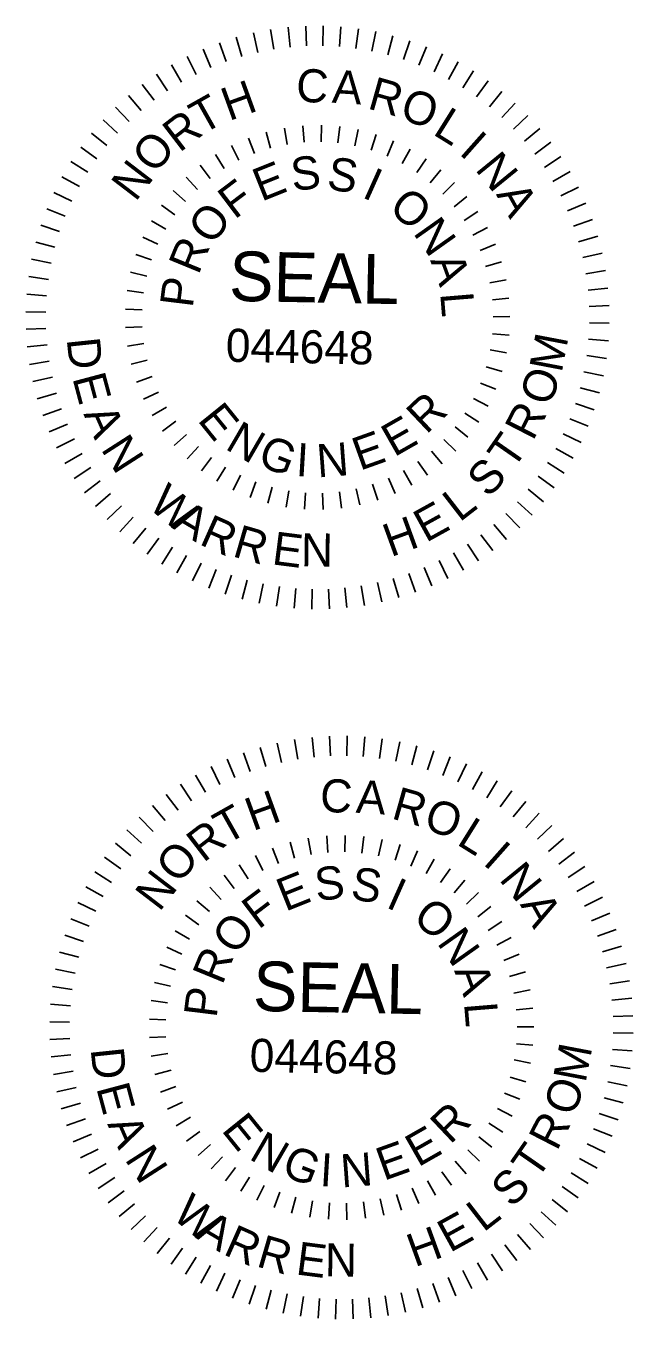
# Model space of a CAD drawing. Extents: x 0 to 7954, y -383 to 1504.
# Drawn here: x 3.6853 to 3.812, y 1.3954 to 1.6653 of the extents above; entities that cross this region are included whole.
import ezdxf

# ---------------------------------------------------------------- set-up
doc = ezdxf.new("R2010")
doc.units = 0
doc.layers.add('UBO Plan Sheet 34 CELL', color=7, linetype='Continuous')

msp = doc.modelspace()

# ---------------------------------------------------------------- linework, layer by layer
at = {"layer": 'UBO Plan Sheet 34 CELL'}
for p, q in [((3.74738, 1.66527), (3.7473, 1.66112)), ((3.72922, 1.66288), (3.73037, 1.65888)), ((3.73279, 1.66379), (3.73369, 1.65974)), ((3.73639, 1.66449), (3.73706, 1.6604)), ((3.74004, 1.66497), (3.74045, 1.66085)), ((3.7437, 1.66523), (3.74387, 1.66109)), ((3.75106, 1.66508), (3.75073, 1.66095)), ((3.75471, 1.66468), (3.75413, 1.66057)), ((3.75833, 1.66406), (3.7575, 1.65999)), ((3.76191, 1.66322), (3.76084, 1.65921)), ((3.7223, 1.6604), (3.72392, 1.65659)), ((3.72572, 1.66175), (3.72712, 1.65783)), ((3.76544, 1.66216), (3.76412, 1.65822)), ((3.76888, 1.66089), (3.76733, 1.65704)), ((3.71896, 1.65886), (3.72082, 1.65515)), ((3.77225, 1.65941), (3.77048, 1.65566)), ((3.77552, 1.65774), (3.77352, 1.6541)), ((3.7126, 1.65518), (3.71489, 1.65172)), ((3.71572, 1.65712), (3.7178, 1.65353)), ((3.77869, 1.65587), (3.77647, 1.65236)), ((3.7096, 1.65306), (3.71209, 1.64975)), ((3.78174, 1.65381), (3.77931, 1.65045)), ((3.70672, 1.65076), (3.70941, 1.64761)), ((3.78465, 1.65158), (3.78203, 1.64836)), ((3.78743, 1.64916), (3.78462, 1.64612)), ((3.704, 1.6483), (3.70687, 1.64531)), ((3.79006, 1.64659), (3.78707, 1.64372)), ((3.70143, 1.64567), (3.70447, 1.64286)), ((3.73925, 1.64393), (3.73984, 1.64052)), ((3.74309, 1.64441), (3.74336, 1.64097)), ((3.74697, 1.64452), (3.7469, 1.64107)), ((3.7469, 1.64107), (3.74697, 1.64452)), ((3.75084, 1.64426), (3.75044, 1.64083)), ((3.79252, 1.64387), (3.78937, 1.64118)), ((3.69901, 1.64289), (3.70223, 1.64027)), ((3.73179, 1.64186), (3.73303, 1.63863)), ((3.73547, 1.64308), (3.73639, 1.63974)), ((3.75466, 1.64362), (3.75393, 1.64024)), ((3.7584, 1.64262), (3.75735, 1.63933)), ((3.76204, 1.64127), (3.76067, 1.63809)), ((3.79483, 1.64099), (3.79151, 1.6385)), ((3.69678, 1.63998), (3.70014, 1.63755)), ((3.72486, 1.6384), (3.7267, 1.63547)), ((3.72824, 1.6403), (3.72978, 1.63721)), ((3.76552, 1.63956), (3.76386, 1.63653)), ((3.69472, 1.63693), (3.69823, 1.63471)), ((3.72168, 1.63618), (3.72379, 1.63344)), ((3.76882, 1.63753), (3.76687, 1.63467)), ((3.79694, 1.63799), (3.79349, 1.6357)), ((3.69285, 1.63376), (3.69649, 1.63176)), ((3.71873, 1.63367), (3.7211, 1.63115)), ((3.77191, 1.63519), (3.76969, 1.63253)), ((3.79888, 1.63487), (3.79529, 1.63279)), ((3.69118, 1.63049), (3.69493, 1.62871)), ((3.71603, 1.63089), (3.71863, 1.62861)), ((3.77476, 1.63256), (3.77229, 1.63013)), ((3.80062, 1.63163), (3.79691, 1.62977)), ((3.71362, 1.62786), (3.71642, 1.62583)), ((3.77734, 1.62967), (3.77466, 1.6275)), ((3.80216, 1.62829), (3.79835, 1.62667)), ((3.6897, 1.62712), (3.69355, 1.62557)), ((3.77964, 1.62655), (3.77675, 1.62463)), ((3.80351, 1.62487), (3.7996, 1.62347)), ((3.68843, 1.62367), (3.69237, 1.62236)), ((3.71151, 1.62461), (3.71449, 1.62286)), ((3.78161, 1.62322), (3.77856, 1.62159)), ((3.68737, 1.62015), (3.69138, 1.61908)), ((3.70972, 1.62116), (3.71286, 1.61972)), ((3.78327, 1.6197), (3.78007, 1.61839)), ((3.80464, 1.62137), (3.80065, 1.62022)), ((3.70828, 1.61756), (3.71155, 1.61643)), ((3.80555, 1.6178), (3.80151, 1.6169)), ((3.68653, 1.61657), (3.6906, 1.61574)), ((3.78457, 1.61605), (3.78125, 1.61505)), ((3.80625, 1.6142), (3.80216, 1.61353)), ((3.68591, 1.61295), (3.69002, 1.61237)), ((3.70718, 1.61385), (3.71054, 1.61303)), ((3.78551, 1.61229), (3.78212, 1.61162)), ((3.68551, 1.60929), (3.68964, 1.60896)), ((3.70646, 1.61004), (3.70988, 1.60956)), ((3.80673, 1.61055), (3.80261, 1.61014)), ((3.7061, 1.60618), (3.70955, 1.60602)), ((3.74334, 1.60681), (3.74334, 1.60681)), ((3.78609, 1.60846), (3.78265, 1.60812)), ((3.80699, 1.60689), (3.80285, 1.60672)), ((3.68532, 1.60562), (3.68947, 1.60554)), ((3.78629, 1.60459), (3.78284, 1.60457)), ((3.80703, 1.60321), (3.80288, 1.60329)), ((3.68536, 1.60194), (3.6895, 1.60211)), ((3.70611, 1.6023), (3.70956, 1.60248)), ((3.78612, 1.60072), (3.78268, 1.60103)), ((3.68562, 1.59828), (3.68974, 1.59869)), ((3.70651, 1.59845), (3.70992, 1.59896)), ((3.80685, 1.59953), (3.80271, 1.59986)), ((3.6861, 1.59463), (3.69019, 1.5953)), ((3.70727, 1.59464), (3.71062, 1.59548)), ((3.7822, 1.59765), (3.7856, 1.59701)), ((3.80644, 1.59588), (3.80234, 1.59646)), ((3.78467, 1.59311), (3.78135, 1.59408)), ((3.80582, 1.59226), (3.80175, 1.59309)), ((3.6868, 1.59103), (3.69085, 1.59193)), ((3.70839, 1.59093), (3.71165, 1.59209)), ((3.7834, 1.58945), (3.78019, 1.59073)), ((3.80498, 1.58868), (3.80097, 1.58975)), ((3.68771, 1.58746), (3.69171, 1.58861)), ((3.70987, 1.58735), (3.713, 1.58883)), ((3.78177, 1.58593), (3.77871, 1.58752)), ((3.68884, 1.58396), (3.69276, 1.58536)), ((3.71168, 1.58393), (3.71466, 1.58569)), ((3.77983, 1.58258), (3.77693, 1.58446)), ((3.80392, 1.58515), (3.79998, 1.58647)), ((3.69019, 1.58054), (3.694, 1.58216)), ((3.71382, 1.58069), (3.71661, 1.58274)), ((3.77756, 1.57943), (3.77486, 1.58158)), ((3.80265, 1.58171), (3.7988, 1.58326)), ((3.69173, 1.5772), (3.69544, 1.57906)), ((3.71627, 1.57768), (3.71884, 1.57998)), ((3.775, 1.57652), (3.77252, 1.57892)), ((3.80117, 1.57834), (3.79742, 1.58011)), ((3.71898, 1.57492), (3.72133, 1.57746)), ((3.77218, 1.57387), (3.76994, 1.5765)), ((3.7995, 1.57507), (3.79586, 1.57707)), ((3.69347, 1.57396), (3.69706, 1.57604)), ((3.72196, 1.57244), (3.72404, 1.57519)), ((3.76911, 1.5715), (3.76713, 1.57434)), ((3.79763, 1.5719), (3.79413, 1.57412)), ((3.69541, 1.57084), (3.69887, 1.57312)), ((3.72515, 1.57025), (3.72697, 1.57319)), ((3.72856, 1.56838), (3.73007, 1.57149)), ((3.76235, 1.56771), (3.76096, 1.57087)), ((3.76583, 1.56944), (3.76413, 1.57246)), ((3.79557, 1.56885), (3.79221, 1.57128)), ((3.69753, 1.56784), (3.70084, 1.57033)), ((3.73212, 1.56684), (3.73333, 1.57008)), ((3.73668, 1.56901), (3.73578, 1.56566)), ((3.7396, 1.56484), (3.74016, 1.56825)), ((3.755, 1.56528), (3.75424, 1.56866)), ((3.75873, 1.56631), (3.75765, 1.5696)), ((3.79334, 1.56594), (3.79012, 1.56856)), ((3.69983, 1.56496), (3.70298, 1.56765)), ((3.74344, 1.56439), (3.74368, 1.56784)), ((3.74732, 1.56431), (3.74722, 1.56777)), ((3.75118, 1.56461), (3.75075, 1.56804)), ((3.79092, 1.56316), (3.78788, 1.56597)), ((3.70229, 1.56224), (3.70528, 1.56511)), ((3.70492, 1.55966), (3.70773, 1.56271)), ((3.78835, 1.56053), (3.78548, 1.56352)), ((3.7077, 1.55725), (3.71032, 1.56047)), ((3.78563, 1.55807), (3.78294, 1.56122)), ((3.71061, 1.55502), (3.71304, 1.55838)), ((3.78275, 1.55577), (3.78026, 1.55908)), ((3.71366, 1.55296), (3.71588, 1.55646)), ((3.71683, 1.55109), (3.71883, 1.55473)), ((3.77663, 1.55171), (3.77455, 1.5553)), ((3.77975, 1.55365), (3.77747, 1.5571)), ((3.7201, 1.54942), (3.72188, 1.55317)), ((3.77005, 1.54843), (3.76843, 1.55224)), ((3.77339, 1.54997), (3.77153, 1.55368)), ((3.72347, 1.54794), (3.72502, 1.55179)), ((3.72692, 1.54667), (3.72823, 1.55061)), ((3.73044, 1.54561), (3.73151, 1.54962)), ((3.76313, 1.54595), (3.76198, 1.54994)), ((3.76663, 1.54708), (3.76523, 1.55099)), ((3.73402, 1.54477), (3.73485, 1.54884)), ((3.73764, 1.54415), (3.73822, 1.54825)), ((3.7413, 1.54374), (3.74163, 1.54788)), ((3.74497, 1.54356), (3.74505, 1.54771)), ((3.74865, 1.5436), (3.74848, 1.54774)), ((3.75231, 1.54386), (3.7519, 1.54798)), ((3.75596, 1.54434), (3.75529, 1.54843)), ((3.75957, 1.54504), (3.75866, 1.54908)), ((3.74869, 1.51705), (3.74885, 1.5129)), ((3.75237, 1.51709), (3.75228, 1.51294)), ((3.75604, 1.5169), (3.75571, 1.51277)), ((3.7342, 1.51469), (3.73536, 1.5107)), ((3.73777, 1.51561), (3.73868, 1.51156)), ((3.74138, 1.51631), (3.74204, 1.51222)), ((3.74502, 1.51679), (3.74544, 1.51266)), ((3.75969, 1.5165), (3.75912, 1.51239)), ((3.76332, 1.51588), (3.76249, 1.51181)), ((3.76689, 1.51503), (3.76583, 1.51102)), ((3.72729, 1.51222), (3.72891, 1.5084)), ((3.73071, 1.51356), (3.73211, 1.50965)), ((3.77042, 1.51398), (3.76911, 1.51003)), ((3.77387, 1.51271), (3.77232, 1.50886)), ((3.72071, 1.50893), (3.72279, 1.50534)), ((3.72395, 1.51068), (3.7258, 1.50696)), ((3.77723, 1.51123), (3.77546, 1.50748)), ((3.78051, 1.50956), (3.77851, 1.50592)), ((3.71758, 1.507), (3.71987, 1.50354)), ((3.78368, 1.50769), (3.78146, 1.50418)), ((3.71458, 1.50488), (3.71707, 1.50157)), ((3.78672, 1.50563), (3.7843, 1.50226)), ((3.78964, 1.50339), (3.78702, 1.50018)), ((3.71171, 1.50258), (3.7144, 1.49942)), ((3.79242, 1.50098), (3.78961, 1.49793)), ((3.70898, 1.50011), (3.71186, 1.49712)), ((3.79504, 1.49841), (3.79205, 1.49554)), ((3.70641, 1.49749), (3.70946, 1.49468)), ((3.74424, 1.49575), (3.74483, 1.49234)), ((3.74808, 1.49623), (3.74834, 1.49278)), ((3.75196, 1.49634), (3.75189, 1.49289)), ((3.75189, 1.49289), (3.75196, 1.49634)), ((3.75583, 1.49607), (3.75542, 1.49264)), ((3.75965, 1.49544), (3.75892, 1.49206)), ((3.79751, 1.49568), (3.79435, 1.493)), ((3.704, 1.49471), (3.70721, 1.49209)), ((3.73677, 1.49368), (3.73801, 1.49045)), ((3.74046, 1.4949), (3.74138, 1.49156)), ((3.76339, 1.49444), (3.76234, 1.49114)), ((3.76702, 1.49308), (3.76566, 1.4899)), ((3.79981, 1.49281), (3.79649, 1.49032)), ((3.70176, 1.4918), (3.70513, 1.48937)), ((3.72984, 1.49022), (3.73168, 1.48728)), ((3.73323, 1.49212), (3.73477, 1.48902)), ((3.7705, 1.49138), (3.76884, 1.48835)), ((3.80193, 1.48981), (3.79847, 1.48752)), ((3.69971, 1.48875), (3.70321, 1.48653)), ((3.72666, 1.488), (3.72878, 1.48526)), ((3.77381, 1.48935), (3.77186, 1.48649)), ((3.69783, 1.48558), (3.70147, 1.48358)), ((3.72371, 1.48549), (3.72608, 1.48296)), ((3.7769, 1.48701), (3.77468, 1.48435)), ((3.80386, 1.48669), (3.80027, 1.4846)), ((3.69617, 1.4823), (3.69991, 1.48053)), ((3.72102, 1.4827), (3.72361, 1.48042)), ((3.77974, 1.48438), (3.77728, 1.48195)), ((3.80561, 1.48344), (3.80189, 1.48159)), ((3.7186, 1.47967), (3.72141, 1.47765)), ((3.78233, 1.48149), (3.77964, 1.47931)), ((3.80715, 1.48011), (3.80333, 1.47848)), ((3.69468, 1.47894), (3.69854, 1.47739)), ((3.7165, 1.47642), (3.71948, 1.47467)), ((3.78462, 1.47836), (3.78174, 1.47645)), ((3.80849, 1.47668), (3.80458, 1.47529)), ((3.69342, 1.47549), (3.69736, 1.47418)), ((3.7866, 1.47503), (3.78355, 1.47341)), ((3.69236, 1.47196), (3.69637, 1.4709)), ((3.71471, 1.47298), (3.71785, 1.47154)), ((3.78825, 1.47152), (3.78505, 1.4702)), ((3.80962, 1.47319), (3.80563, 1.47203)), ((3.69152, 1.46839), (3.69558, 1.46756)), ((3.71326, 1.46938), (3.71653, 1.46825)), ((3.81054, 1.46962), (3.80649, 1.46872)), ((3.71217, 1.46566), (3.71553, 1.46485)), ((3.78955, 1.46787), (3.78624, 1.46687)), ((3.81124, 1.46601), (3.80714, 1.46535)), ((3.6909, 1.46476), (3.695, 1.46419)), ((3.7905, 1.46411), (3.78711, 1.46343)), ((3.69049, 1.46111), (3.69462, 1.46078)), ((3.71144, 1.46185), (3.71486, 1.46138)), ((3.79107, 1.46028), (3.78764, 1.45993)), ((3.81172, 1.46237), (3.80759, 1.46195)), ((3.69031, 1.45744), (3.69445, 1.45736)), ((3.71108, 1.45799), (3.71453, 1.45784)), ((3.74833, 1.45863), (3.74833, 1.45863)), ((3.81198, 1.4587), (3.80783, 1.45854)), ((3.79128, 1.45641), (3.78782, 1.45639)), ((3.81202, 1.45503), (3.80787, 1.45511)), ((3.69034, 1.45376), (3.69449, 1.45393)), ((3.7111, 1.45412), (3.71455, 1.4543)), ((3.79111, 1.45253), (3.78767, 1.45285)), ((3.69061, 1.45009), (3.69473, 1.45051)), ((3.71149, 1.45026), (3.71491, 1.45078)), ((3.78719, 1.44947), (3.79059, 1.44882)), ((3.81183, 1.45135), (3.8077, 1.45168)), ((3.69108, 1.44645), (3.69518, 1.44711)), ((3.71225, 1.44646), (3.7156, 1.4473)), ((3.81142, 1.4477), (3.80732, 1.44828)), ((3.78965, 1.44492), (3.78634, 1.4459)), ((3.8108, 1.44408), (3.80674, 1.4449)), ((3.69178, 1.44284), (3.69583, 1.44375)), ((3.71338, 1.44275), (3.71663, 1.44391)), ((3.78838, 1.44126), (3.78517, 1.44255)), ((3.80996, 1.4405), (3.80595, 1.44157)), ((3.6927, 1.43928), (3.69669, 1.44043)), ((3.71486, 1.43917), (3.71798, 1.44064)), ((3.78676, 1.43775), (3.7837, 1.43934)), ((3.69383, 1.43578), (3.69774, 1.43718)), ((3.71667, 1.43575), (3.71964, 1.43751)), ((3.78482, 1.4344), (3.78191, 1.43627)), ((3.80891, 1.43697), (3.80496, 1.43829)), ((3.69518, 1.43236), (3.69899, 1.43398)), ((3.71881, 1.43251), (3.7216, 1.43455)), ((3.78255, 1.43124), (3.77984, 1.4334)), ((3.80764, 1.43353), (3.80378, 1.43508)), ((3.69671, 1.42902), (3.70043, 1.43087)), ((3.72125, 1.4295), (3.72383, 1.4318)), ((3.77999, 1.42834), (3.77751, 1.43074)), ((3.80616, 1.43016), (3.80241, 1.43193)), ((3.69846, 1.42578), (3.70205, 1.42786)), ((3.72396, 1.42674), (3.72631, 1.42928)), ((3.77717, 1.42568), (3.77492, 1.42832)), ((3.80449, 1.42688), (3.80085, 1.42888)), ((3.72694, 1.42425), (3.72903, 1.42701)), ((3.77409, 1.42332), (3.77212, 1.42615)), ((3.80262, 1.42371), (3.79911, 1.42594)), ((3.70039, 1.42265), (3.70385, 1.42494)), ((3.73014, 1.42206), (3.73196, 1.42501)), ((3.73354, 1.4202), (3.73506, 1.4233)), ((3.76734, 1.41953), (3.76595, 1.42269)), ((3.77081, 1.42126), (3.76911, 1.42427)), ((3.80056, 1.42067), (3.79719, 1.42309)), ((3.70251, 1.41965), (3.70583, 1.42214)), ((3.7371, 1.41866), (3.73832, 1.4219)), ((3.74166, 1.42082), (3.74077, 1.41748)), ((3.74458, 1.41666), (3.74515, 1.42007)), ((3.74843, 1.41621), (3.74866, 1.41966)), ((3.75617, 1.41643), (3.75574, 1.41986)), ((3.75999, 1.4171), (3.75922, 1.42048)), ((3.76372, 1.41813), (3.76264, 1.42142)), ((3.79832, 1.41776), (3.79511, 1.42037)), ((3.70481, 1.41678), (3.70797, 1.41947)), ((3.7523, 1.41613), (3.75221, 1.41959)), ((3.79591, 1.41497), (3.79286, 1.41779)), ((3.70728, 1.41406), (3.71027, 1.41693)), ((3.7099, 1.41148), (3.71272, 1.41453)), ((3.79334, 1.41235), (3.79046, 1.41534)), ((3.71268, 1.40907), (3.7153, 1.41228)), ((3.79061, 1.40988), (3.78792, 1.41304)), ((3.7156, 1.40683), (3.71802, 1.4102)), ((3.78474, 1.40546), (3.78245, 1.40892)), ((3.78774, 1.40758), (3.78525, 1.4109)), ((3.71864, 1.40478), (3.72086, 1.40828)), ((3.72181, 1.40291), (3.72381, 1.40654)), ((3.78161, 1.40353), (3.77953, 1.40712)), ((3.72509, 1.40124), (3.72686, 1.40498)), ((3.72845, 1.39976), (3.73001, 1.40361)), ((3.77503, 1.40025), (3.77341, 1.40406)), ((3.77837, 1.40178), (3.77652, 1.4055)), ((3.7319, 1.39849), (3.73321, 1.40243)), ((3.73543, 1.39743), (3.73649, 1.40144)), ((3.76455, 1.39685), (3.76364, 1.4009)), ((3.76812, 1.39777), (3.76696, 1.40176)), ((3.77161, 1.3989), (3.77021, 1.40281)), ((3.73901, 1.39659), (3.73983, 1.40065)), ((3.74263, 1.39597), (3.74321, 1.40007)), ((3.74628, 1.39556), (3.74661, 1.3997)), ((3.74995, 1.39538), (3.75004, 1.39953)), ((3.75363, 1.39542), (3.75347, 1.39956)), ((3.7573, 1.39568), (3.75688, 1.3998)), ((3.76094, 1.39615), (3.76028, 1.40025))]:
    msp.add_line(p, q, dxfattribs=at)

# ---------------------------------------------------------------- texts
for s, height, rotation, p in [('C', 0.00691, 356.2217, (3.74154, 1.64954)), ('A', 0.00691, 356.2217, (3.74909, 1.64925)), ('R', 0.00691, 344.2124, (3.75639, 1.64809)), ('H', 0.00691, 19.9324, (3.72771, 1.64537)), ('O', 0.00691, 341.1556, (3.76304, 1.64597)), ('T', 0.00691, 29.3644, (3.72208, 1.64248)), ('R', 0.00691, 37.5253, (3.71736, 1.6387)), ('L', 0.00691, 328.0193, (3.77001, 1.64275)), ('O', 0.00691, 50.5821, (3.71227, 1.63415)), ('I', 0.00691, 318.4439, (3.7755, 1.63863)), ('N', 0.00691, 309.1494, (3.77889, 1.63531)), ('N', 0.00691, 52.5415, (3.70818, 1.62839)), ('E', 0.00691, 21.8091, (3.73446, 1.62855)), ('S', 0.00691, 6.5129, (3.741, 1.63079)), ('S', 0.00691, 351.2166, (3.74791, 1.63123)), ('I', 0.00691, 335.9204, (3.75522, 1.62959)), ('F', 0.00691, 37.1054, (3.72886, 1.62475)), ('O', 0.00691, 320.6242, (3.76074, 1.62679)), ('A', 0.00691, 299.3819, (3.78335, 1.63012)), ('O', 0.00691, 52.4016, (3.72415, 1.61927)), ('N', 0.00691, 305.3279, (3.76597, 1.62206)), ('R', 0.00691, 67.6979, (3.7213, 1.61312)), ('SEAL', 0.010372, 358.8648, (3.72766, 1.60789)), ('A', 0.00691, 290.0317, (3.76965, 1.61633)), ('P', 0.00691, 82.9941, (3.72012, 1.60629)), ('L', 0.00691, 274.7354, (3.77175, 1.60945)), ('044648', 0.006909, 358.8648, (3.72698, 1.59519)), ('M', 0.00691, 79.1773, (3.7971, 1.59272)), ('D', 0.00691, 275.9811, (3.69383, 1.59991)), ('E', 0.00691, 284.9836, (3.69499, 1.59181)), ('O', 0.00691, 71.1829, (3.79472, 1.58569)), ('R', 0.00691, 43.4297, (3.76884, 1.57988)), ('A', 0.00691, 293.8062, (3.69729, 1.58429)), ('E', 0.00691, 308.9349, (3.72098, 1.58297)), ('R', 0.00691, 62.7337, (3.79111, 1.57847)), ('N', 0.00691, 329.7899, (3.72667, 1.57709)), ('E', 0.00691, 29.6586, (3.76216, 1.5752)), ('N', 0.00691, 302.6889, (3.70085, 1.57695)), ('G', 0.00691, 338.5562, (3.73337, 1.57372)), ('E', 0.00691, 19.6727, (3.75501, 1.57239)), ('T', 0.00691, 55.228, (3.78693, 1.57238)), ('I', 0.00691, 356.651, (3.74155, 1.57135)), ('N', 0.00691, 4.2806, (3.74623, 1.57102)), ('S', 0.00691, 46.5552, (3.78179, 1.56658)), ('W', 0.00691, 320.3641, (3.71061, 1.56485)), ('E', 0.00691, 28.88, (3.76879, 1.55734)), ('L', 0.00691, 37.7626, (3.7758, 1.56158)), ('A', 0.00691, 329.3125, (3.71556, 1.56059)), ('R', 0.00691, 336.0279, (3.72128, 1.55716)), ('H', 0.00691, 19.9974, (3.76146, 1.55436)), ('R', 0.00691, 343.8077, (3.7282, 1.55463)), ('E', 0.00691, 352.7158, (3.73649, 1.55292)), ('N', 0.00691, 359.3001, (3.74269, 1.55249)), ('C', 0.00691, 356.2217, (3.74653, 1.50136)), ('A', 0.00691, 356.2217, (3.75407, 1.50107)), ('R', 0.00691, 344.2124, (3.76137, 1.49991)), ('H', 0.00691, 19.9324, (3.73269, 1.49719)), ('O', 0.00691, 341.1556, (3.76802, 1.49779)), ('T', 0.00691, 29.3644, (3.72707, 1.49429)), ('R', 0.00691, 37.5253, (3.72235, 1.49052)), ('L', 0.00691, 328.0193, (3.77499, 1.49457)), ('O', 0.00691, 50.5821, (3.71725, 1.48597)), ('I', 0.00691, 318.4439, (3.78048, 1.49045)), ('S', 0.00691, 6.5129, (3.74598, 1.48261)), ('N', 0.00691, 309.1494, (3.78388, 1.48712)), ('N', 0.00691, 52.5415, (3.71317, 1.48021)), ('E', 0.00691, 21.8091, (3.73945, 1.48037)), ('S', 0.00691, 351.2166, (3.75289, 1.48305)), ('I', 0.00691, 335.9204, (3.76021, 1.48141)), ('F', 0.00691, 37.1054, (3.73384, 1.47657)), ('O', 0.00691, 320.6242, (3.76572, 1.47861)), ('A', 0.00691, 299.3819, (3.78834, 1.48193)), ('O', 0.00691, 52.4016, (3.72914, 1.47109)), ('N', 0.00691, 305.3279, (3.77095, 1.47388)), ('R', 0.00691, 67.6979, (3.72628, 1.46494)), ('SEAL', 0.010372, 358.8648, (3.73264, 1.45971)), ('A', 0.00691, 290.0317, (3.77463, 1.46815)), ('P', 0.00691, 82.9941, (3.7251, 1.45811)), ('L', 0.00691, 274.7354, (3.77673, 1.46126)), ('044648', 0.006909, 358.8648, (3.73196, 1.44701)), ('M', 0.00691, 79.1773, (3.80208, 1.44454)), ('D', 0.00691, 275.9811, (3.69882, 1.45173)), ('E', 0.00691, 284.9836, (3.69998, 1.44363)), ('O', 0.00691, 71.1829, (3.7997, 1.43751)), ('E', 0.00691, 308.9349, (3.72597, 1.43478)), ('R', 0.00691, 43.4297, (3.77382, 1.4317)), ('A', 0.00691, 293.8062, (3.70227, 1.43611)), ('R', 0.00691, 62.7337, (3.79609, 1.43028)), ('N', 0.00691, 329.7899, (3.73166, 1.42891)), ('E', 0.00691, 29.6586, (3.76715, 1.42701)), ('N', 0.00691, 302.6889, (3.70583, 1.42877)), ('G', 0.00691, 338.5562, (3.73835, 1.42554)), ('E', 0.00691, 19.6727, (3.76, 1.42421)), ('T', 0.00691, 55.228, (3.79192, 1.4242)), ('I', 0.00691, 356.651, (3.74654, 1.42316)), ('N', 0.00691, 4.2806, (3.75122, 1.42284)), ('S', 0.00691, 46.5552, (3.78678, 1.4184)), ('W', 0.00691, 320.3641, (3.71559, 1.41667)), ('L', 0.00691, 37.7626, (3.78079, 1.41339)), ('A', 0.00691, 329.3125, (3.72054, 1.41241)), ('E', 0.00691, 28.88, (3.77378, 1.40916)), ('R', 0.00691, 336.0279, (3.72627, 1.40898)), ('H', 0.00691, 19.9974, (3.76645, 1.40618)), ('R', 0.00691, 343.8077, (3.73319, 1.40645)), ('E', 0.00691, 352.7158, (3.74148, 1.40473)), ('N', 0.00691, 359.3001, (3.74768, 1.4043))]:
    msp.add_text(s, height=height, rotation=rotation, dxfattribs=at).set_placement(p)

doc.saveas('drawing.dxf')
